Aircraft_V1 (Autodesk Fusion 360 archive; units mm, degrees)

design "Aircraft_V1" references "Extra_540_rear_tags"
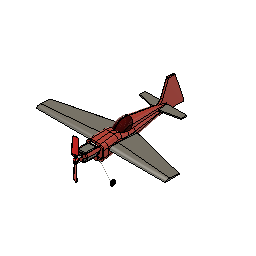
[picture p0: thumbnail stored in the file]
canvas "Canvas1"
canvas "Canvas2"
canvas "Canvas3"
component_insert "Component Insert"
ground "Ground4"
sketch "Sketch1" plane through (0, 0, 0) normal (1, 0, 0) x axis (0, 0, -1)
extrude "Extrude1" new body sketch "Sketch1" along normal blind 16
sketch "Sketch2" plane through (0, 0, 0) normal (0, 1, 0) x axis (1, 0, 0)
extrude "Extrude2" cut sketch "Sketch2" no distance stored
fillet "Fillet1" radius 20
fillet "Fillet2" radius 7
fillet "Fillet3" radius 10
sketch "Sketch4" plane through (0, 0, 0) normal (1, 0, 0) x axis (0, 0, -1)
extrude "Extrude3" new body sketch "Sketch4" along normal blind 10.5
chamfer "Chamfer1" distance 86.5 distance 9.4
fillet "Fillet4" StartRadius 1 EndRadius 9.25
revolve "Revolve1" AlongAngle 120
sketch "Sketch5" plane through (0, 0, 0) normal (1, 0, 0) x axis (0, 0, -1)
extrude "Extrude4" add sketch "Sketch5" along normal blind 2
fillet "Fillet5" radius 4
fillet "Fillet6" radius 2
sketch "Sketch8" plane through (0, 0, 0) normal (1, 0, 0) x axis (0, 0, -1)
  dimension "d166" = 2
extrude "Extrude5" cut sketch "Sketch8" no distance stored
mirror_component "MirrorComponent1"
derived_instance "DerivedInstance1"
sketch "Sketch1" plane through (0, 0, 0) normal (1, 0, 0) x axis (0, 0, -1)
extrude "Extrude1" new body sketch "Sketch1" along normal blind 16
work_plane "WorkPlane1" AlongDistance 125
sketch "Sketch2" plane through (125, 0, 0) normal (1, 0, 0) x axis (0, 0, -1)
  dimension "d175" = 2
loft "Loft1" sketch "Sketch2"
mirror "Mirror1"
sketch "Sketch1" plane through (0, 3.9393, 0) normal (0, 1, 0) x axis (-1, 0, 0)
extrude "Extrude1" new body sketch "Sketch1" along normal blind 2
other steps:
derived_base_feature "Derived Base Feature"
create_component "CreateComponent4"
create_component "CreateComponent5"
create_component "CreateComponent9"
create_component "CreateComponent12"

design "Extra_540_freeform_Undercarriage"
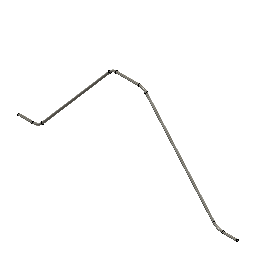
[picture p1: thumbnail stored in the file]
base_feature "Base Feature"
sketch "Path (1)" plane through (0, 0, -48.1) normal (0, 0, 1) x axis (1, 0, 0)
  dimension "d165" = 5
  dimension "d166" = 4
  dimension "d178" = 0
  dimension "d179" = 0
  dimension "d180" = 0
  dimension "d181" = 0
  dimension "d190" = 0
  dimension "d191" = 0
  dimension "d192" = 0
  dimension "d193" = 0
sketch "Profile" plane through (0, 0, 0) normal (1, 0, 0) x axis (0, 0, -1)
  circle C1 centre (47.7, -10.2807) radius 0.375
  dimension "d167" diameter C1 = 0.75
sweep "Sweep1" sketch "Profile" TwistAngle 0 TaperAngle 0

design "Propeller_3_x_1"
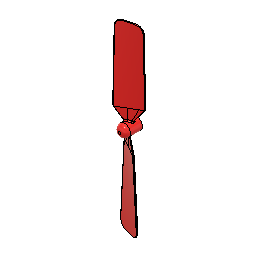
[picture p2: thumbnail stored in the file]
sketch "Sketch1" plane through (0, 0, 0) normal (1, 0, 0) x axis (0, 0, -1)
  dimension "d1" = 1
  dimension "d2" = 2.5
  dimension "d3" = 2
  dimension "d5" = 7
  dimension "d6" = 115
  dimension "d7" = 1.5
revolve "Revolve1" sketch "Sketch1" AlongAngle 360
work_plane "WorkPlane1" AlongDistance 38
sketch "Sketch2" plane through (0, 38, 0) normal (0, 1, 0) x axis (1, 0, 0)
  dimension "d10" = 3
  dimension "d11" = 10
  dimension "d12" = 0.5
  dimension "d13" = 10
work_plane "WorkPlane2" AlongDistance 7
sketch "Sketch3" plane through (0, 7, 0) normal (0, 1, 0) x axis (1, 0, 0)
  dimension "d15" = 10
  dimension "d16" = 0.5
  dimension "d17" = 30
sketch "Sketch4" plane through (0, 0, 0) normal (1, 0, 0) x axis (0, 0, -1)
sweep "Sweep1" sketch "Sketch3" TwistAngle -15 TaperAngle 0
sketch "Sketch5" plane through (0, 0, 0) normal (0, 1, 0) x axis (1, 0, 0)
  dimension "d24" = 0.5
  dimension "d25" = 1
  dimension "d26" = 60
sketch "Sketch6" plane through (0, 0, 0) normal (1, 0, 0) x axis (0, 0, -1)
loft "Loft2" sketch "Sketch5" + "Sketch3"
fillet "Fillet2" radius 3
fillet "Fillet3" radius 2
fillet "Fillet4" radius 0.2
fillet "Fillet5" radius 0.5
circular_pattern "C-Pattern1" TotalAngle 360

design "Extra_540_rear_tags" references "Extra_540_freeform_Undercarriage", "Motor_prop_rear_tags", "Sleeve", "Extra_540_wheel"
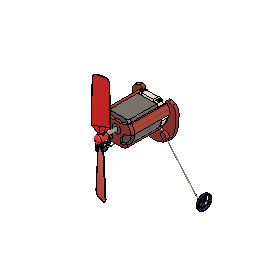
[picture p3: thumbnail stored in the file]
canvas "Canvas1"
canvas "Canvas2"
canvas "Canvas3"
component_insert "Component Insert4"
position "Position2"
base_feature "Base Feature"
work_plane "WorkPlane1" AlongDistance -50.1
sketch "Sketch3" plane through (0, 0, -50.1) normal (0, 0, 1) x axis (1, 0, 0)
extrude "Extrude1" new body sketch "Sketch3" along normal blind 2 taper -5
sketch "Sketch12" plane through (0, 0, -48.1) normal (0, 0, 1) x axis (1, 0, 0)
extrude "Extrude9" cut sketch "Sketch12" no distance stored
sketch "Sketch13" plane through (0, 0, -48.1) normal (0, 0, 1) x axis (1, 0, 0)
  dimension "d100" = 2
  dimension "d104" = 1.5
  dimension "d105" = 6
  dimension "d106" = 12
extrude "Extrude10" add sketch "Sketch13" along normal blind 25
sketch "Sketch14" plane through (0, 0, -23.1) normal (0, 0, 1) x axis (1, 0, 0)
  dimension "d109" = 6.0836
  dimension "d110" = 10
extrude "Extrude11" add sketch "Sketch14" along normal blind 1.5
sketch "Sketch7" plane through (0, 0, -48.1) normal (0, 0, 1) x axis (1, 0, 0)
  dimension "d141" = 4
  dimension "d143" = 4
  dimension "d144" = 2.5
  dimension "d113" = 2
  dimension "d114" = 8
extrude "Extrude5" add sketch "Sketch7" along normal blind 2.5
fillet "Fillet2" radius 1
sketch "Sketch8" plane through (4.0871, 0, 0) normal (1, 0, 0) x axis (0, 0, -1)
sketch "Sketch9" plane through (4.0871, 0, 0) normal (1, 0, 0) x axis (0, 0, -1)
  dimension "d148" = 0.4
  dimension "d149" = 0.8
extrude "Extrude6" cut sketch "Sketch9" to an object
sketch "Sketch10" plane through (0, 0, -48.1) normal (0, 0, 1) x axis (1, 0, 0)
  dimension "d154" = 29.9506
  dimension "d155" = 26.0609
  dimension "d161" = 2.5
  dimension "d162" = 3.5
extrude "Extrude7" add sketch "Sketch10" along normal blind 0.8
sketch "Sketch11" plane through (0, 0, -47.3) normal (0, 0, 1) x axis (1, 0, 0)
  dimension "d164" = 1
extrude "Extrude8" add sketch "Sketch11" along normal blind 1.5
fillet "Fillet3" radius 2
chamfer "Chamfer2" distance 0.5
fillet "Fillet4" radius 1.5
joint "Assemble11" OffsetX 0 OffsetY 0 OffsetZ 0 AngleZ 0 alignAngle 180 alignOffsetX 0 alignOffsetY 0 alignOffsetZ 0
ground "Ground7"
component_insert "Component Insert13"
joint "Assemble12" OffsetX 0 OffsetY 0 OffsetZ 0 AngleZ 0 alignAngle 0 alignOffsetX 0 alignOffsetY 0 alignOffsetZ 0
component_insert "Component Insert14"
joint "Assemble13" OffsetX 0 OffsetY 0 OffsetZ 0 AngleZ 0 OffsetX 0 OffsetY 0 OffsetZ 0 AngleZ 0 alignAngle -90 alignOffsetX 0 alignOffsetY 0 alignOffsetZ 0
component_insert "Component Insert15"
joint "Assemble14" OffsetX 0 OffsetY 0 OffsetZ 0 AngleZ 0 OffsetX 0 OffsetY 0 OffsetZ 0 AngleZ 0 alignAngle -90 alignOffsetX 0 alignOffsetY 0 alignOffsetZ 0
component_insert "Component Insert16"
component_insert "Component Insert17"
joint "Assemble15" OffsetX 0 OffsetY 0 OffsetZ 0 AngleZ 0 OffsetX 0 OffsetY 0 OffsetZ 0 AngleZ 0 alignAngle -90 alignOffsetX 0 alignOffsetY 0 alignOffsetZ 0
joint "Assemble16" OffsetX 0 OffsetY 0 OffsetZ 0 AngleZ 0 OffsetX 0 OffsetY 0 OffsetZ 0 AngleZ 0 alignAngle -90 alignOffsetX 0 alignOffsetY 0 alignOffsetZ 0
component_insert "Component Insert18"
joint "Assemble17" OffsetX 0 OffsetY 0 OffsetZ 0 AngleZ 0 OffsetX 0 OffsetY 0 OffsetZ 0 AngleZ 0 alignAngle 0 alignOffsetX 0 alignOffsetY 0 alignOffsetZ 0
component_insert "Component Insert19"
joint "Assemble18" OffsetX 0 OffsetY 0 OffsetZ 0 AngleZ 0 OffsetX 0 OffsetY 0 OffsetZ 0 AngleZ 0 alignAngle 0 alignOffsetX 0 alignOffsetY 0 alignOffsetZ 0
component_insert "Component Insert6"
joint "Assemble1" OffsetX 0 OffsetY 0 OffsetZ 0 AngleZ 0 alignAngle 0 alignOffsetX 0 alignOffsetY 0 alignOffsetZ 0
joint "Assemble2" OffsetX 0 OffsetY 0 OffsetZ 0 AngleZ 0 alignAngle 0 alignOffsetX 0 alignOffsetY 0 alignOffsetZ 0
component_insert "Component Insert7"
joint "Assemble3" OffsetX 0 OffsetY 0 OffsetZ 0 AngleZ 0 OffsetX 0 OffsetY 0 OffsetZ 0 AngleZ 0 alignAngle -90 alignOffsetX 0 alignOffsetY 0 alignOffsetZ 0
component_insert "Component Insert8"
joint "Assemble4" OffsetX 0 OffsetY 0 OffsetZ 0 AngleZ 0 OffsetX 0 OffsetY 0 OffsetZ 0 AngleZ 0 alignAngle 0 alignOffsetX 0 alignOffsetY 0 alignOffsetZ 0
component_insert "Component Insert9"
joint "Assemble5" OffsetX 0 OffsetY 0 OffsetZ 0 AngleZ 0 OffsetX 0 OffsetY 0 OffsetZ 0 AngleZ 0 alignAngle -90 alignOffsetX 0 alignOffsetY 0 alignOffsetZ 0
component_insert "Component Insert10"
joint "Assemble6" OffsetX 0 OffsetY 0 OffsetZ 0 AngleZ 0 OffsetX 0 OffsetY 0 OffsetZ 0 AngleZ 0 alignAngle -90 alignOffsetX 0 alignOffsetY 0 alignOffsetZ 0
component_insert "Component Insert11"
joint "Assemble7" OffsetX 0 OffsetY 0 OffsetZ 0 AngleZ 0 OffsetX 0 OffsetY 0 OffsetZ 0 AngleZ 0 alignAngle -90 alignOffsetX 0 alignOffsetY 0 alignOffsetZ 0
component_insert "Component Insert12"
joint "Assemble8" OffsetX 0 OffsetY 0 OffsetZ 0 AngleZ 0 OffsetX 0 OffsetY 0 OffsetZ 0 AngleZ 0 alignAngle 0 alignOffsetX 0 alignOffsetY 0 alignOffsetZ 0
ground "Ground4"
ground "Ground5"
position "Position3"
ground "Ground6"
joint "Assemble9" OffsetX 0 OffsetY 0 OffsetZ 0 AngleZ 0 alignAngle 180 alignOffsetX 0 alignOffsetY 0 alignOffsetZ 0
joint "Assemble10" OffsetX 0 OffsetY 0 OffsetZ 0 AngleZ 0 alignAngle 180 alignOffsetX 0 alignOffsetY 0 alignOffsetZ 0
ground "Ground3"
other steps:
create_component "CreateComponent3"
joint_origin "JointOrigin1" OffsetX 0 OffsetY 0 OffsetZ 0 AngleZ 0
joint_origin "JointOrigin2" OffsetX 0 OffsetY 0 OffsetZ 0 AngleZ 0
joint_origin "JointOrigin3" OffsetX 0 OffsetY 0 OffsetZ 0 AngleZ 0
joint_origin "JointOrigin4" OffsetX 0 OffsetY 0 OffsetZ 0 AngleZ 0
joint_origin "JointOrigin5" OffsetX 0 OffsetY 0 OffsetZ 0 AngleZ 0
joint_origin "JointOrigin6" OffsetX 0 OffsetY 0 OffsetZ 0 AngleZ 0

design "Motor_body_rev"
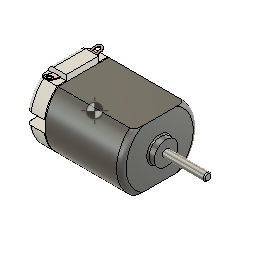
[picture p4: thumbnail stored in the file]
sketch "Sketch1" plane through (0, 0, 0) normal (1, 0, 0) x axis (0, 0, -1)
  dimension "d1" = 20.1
  dimension "d2" = 15.1
extrude "Extrude1" new body sketch "Sketch1" along normal blind 20
sketch "Sketch2" plane through (0, 0, 0) normal (-1, 0, 0) x axis (0, 0, 1)
  dimension "d5" = 1
extrude "Extrude2" add sketch "Sketch2" along normal blind 0.25
sketch "Sketch1"
sketch "Sketch2" plane through (0, 0, 0) normal (1, 0, 0) x axis (0, 0, -1)
work_plane "WorkPlane1"
sketch "Sketch3" plane through (-0.25, 6.55, 6.245) normal (1, 0, 0) x axis (0, 0, -1)
  dimension "d8" = 8.5
  dimension "d9" = 1.4
extrude "Extrude1" new body sketch "Sketch3" against normal blind 4.75
sketch "Sketch4" plane through (-5, 0, 0) normal (-1, 0, 0) x axis (0, 0, 1)
  dimension "d12" = 10
  dimension "d13" = 4
extrude "Extrude2" add sketch "Sketch4" along normal blind 2.3
sketch "Sketch3" plane through (20, 0, 0) normal (1, 0, 0) x axis (0, 0, -1)
  dimension "d16" = 6.15
extrude "Extrude3" add sketch "Sketch3" along normal blind 1.7
sketch "Sketch1" plane through (-7.3, 0, 0) normal (-1, 0, 0) x axis (0, 0, 1)
  dimension "d19" = 2
extrude "Extrude1" new body sketch "Sketch1" along normal blind 2
sketch "Sketch2" plane through (21.7, 0, 0) normal (1, 0, 0) x axis (0, 0, -1)
  circle C1 centre (0, 0) radius 3.075
extrude "Extrude4" cut of existing geometry blind -38
work_plane "WorkPlane1" AlongDistance 2
sketch "Sketch1" plane through (-2, 0, 0) normal (-1, 0, 0) x axis (0, 0, -1)
  dimension "d29" = 3.25
  dimension "d30" = 0.2
  dimension "d31" = 15
extrude "Extrude1" new body sketch "Sketch1" along normal blind 2
fillet "Fillet1" radius 1
sketch "Sketch2" plane through (0, 6.4116, 1.718) normal (0, 0.9659, 0.2588) x axis (1, 0, 0)
  dimension "d36" = 1.5
  dimension "d37" = 0.5
extrude "Extrude2" cut sketch "Sketch2" to an object
sketch "Sketch3" plane through (0, 6.4116, -1.718) normal (0, 0.9659, -0.2588) x axis (-1, 0, 0)
  dimension "d41" = 1.5
  dimension "d42" = 0.5
extrude "Extrude3" cut sketch "Sketch3" to an object
sketch "Sketch5" plane through (-5, 0, 0) normal (-1, 0, 0) x axis (0, 0, 1)
  dimension "d45" = 6
  dimension "d46" = 1
  dimension "d47" = 1
  dimension "d48" = 7
extrude "Extrude4" add sketch "Sketch5" along normal blind 0.1
sketch "Sketch6" plane through (-5, 0, 0) normal (-1, 0, 0) x axis (0, 0, 1)
  dimension "d51" = 3
  dimension "d52" = 4.825
extrude "Extrude5" cut sketch "Sketch6" to an object
fillet "Fillet1" radius 1.25
fillet "Fillet1" radius 1.25
extrude "Extrude3" add of existing geometry blind 40
chamfer "Chamfer1" distance 0.5 rotateAngle 45
fillet "Fillet2" radius 1.4
fillet "Fillet2" radius 0.3
fillet "Fillet1" radius 0.25
ground "Ground1"
joint "Assemble1" alignAngle 0 alignOffsetX 0 alignOffsetY 0 alignOffsetZ 11
move "Move1"
ground "Ground2"
ground "Ground3"
component_from_bodies "Body->Comp"
joint "Assemble5" alignAngle 0 alignOffsetX 0 alignOffsetY 0 alignOffsetZ 0
joint "Assemble6" alignAngle 0 alignOffsetX 0 alignOffsetY 0 alignOffsetZ 0
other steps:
base_feature "Base Feature"
create_component "CreateComponent1"
create_component "CreateComponent2"
extrude "Extrude3" cut of existing geometry blind -38
extrude "Extrude2" cut of existing geometry blind -38
create_component "CreateComponent3"
joint_origin "JointOrigin1" OffsetX 0 OffsetY 0 OffsetZ 0 AngleZ 0
joint_origin "JointOrigin1" OffsetX 0 OffsetY 0 OffsetZ 0 AngleZ 0
create_component "CreateComponent4"
remove_body "RemoveBody1"
joint_origin "JointOrigin3" OffsetX 0 OffsetY 0 OffsetZ 0 AngleZ 0
joint_origin "JointOrigin4" OffsetX 0 OffsetY 0 OffsetZ 0 AngleZ 0
joint_origin "JointOrigin2" OffsetX 0 OffsetY 0 OffsetZ 0 AngleZ 0
joint_origin "JointOrigin5" OffsetX 0 OffsetY 0 OffsetZ 0 AngleZ 0

design "Sleeve"
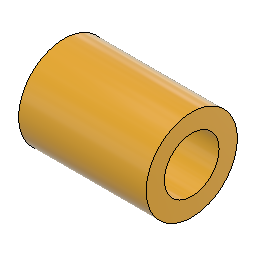
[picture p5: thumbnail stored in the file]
sketch "Sketch1" plane through (0, 0, 0) normal (1, 0, 0) x axis (0, 0, -1)
  circle C1 centre (0, 0) radius 0.375
  circle C2 centre (0, 0) radius 0.625
  dimension "d1" diameter C1 = 0.75
  dimension "d2" diameter C2 = 1.25
extrude "Extrude1" new body sketch "Sketch1" along normal blind 1.75

design "Extra_540_wheel"
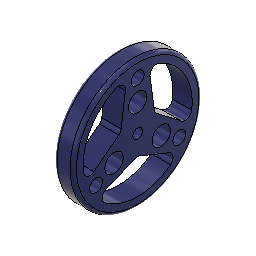
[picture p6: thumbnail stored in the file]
sketch "Sketch1" plane through (0, 0, 0) normal (1, 0, 0) x axis (0, 0, -1)
  dimension "d1" = 0.75
  dimension "d2" = 10
  dimension "d5" = 1
  dimension "d6" = 0.4
  dimension "d7" = 2
extrude "Extrude1" new body sketch "Sketch1" along normal blind 1.5
fillet "Fillet1" radius 0.5
fillet "Fillet2" radius 0.25

design "Motor_prop_rear_tags" references "Propeller_3_x_1", "Motor_body_rev"
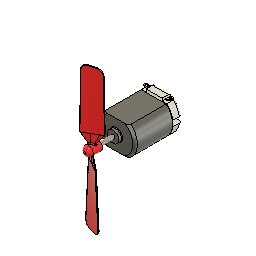
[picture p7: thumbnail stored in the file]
component_insert "Component Insert1"
ground "Ground1"
component_insert "Component Insert2"
joint "Assemble1" OffsetX 0 OffsetY 0 OffsetZ 0 AngleZ 0 OffsetX 0 OffsetY 0 OffsetZ 0 AngleZ 0 alignAngle 180 alignOffsetX 0 alignOffsetY 0 alignOffsetZ 3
